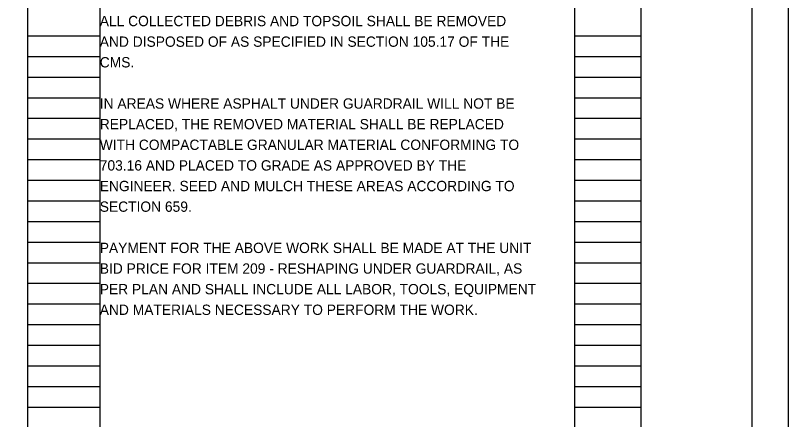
# Model space of a CAD drawing. Extents: x 0 to 34, y 0 to 22.
# Drawn here: x 23.51 to 34, y 5.57 to 11.06 of the extents above; entities that cross this region are included whole.
import ezdxf

# ---------------------------------------------------------------- set-up
doc = ezdxf.new("R2010")
doc.units = 0
for name, color, linetype in [('SH_Border', 7, 'Continuous'), ('SH_Cut_Line', 7, 'Continuous'), ('SH_Data', 7, 'Continuous'), ('SH_Text', 7, 'Continuous')]:
    doc.layers.add(name, color=color, linetype=linetype)

msp = doc.modelspace()

# ---------------------------------------------------------------- linework, layer by layer
at = {"layer": 'SH_Border'}
msp.add_line((32, 0.5), (32, 21.5), dxfattribs=at)
msp.add_lwpolyline([(1.5, 21.5), (33.5, 21.5), (33.5, 0.5), (1.5, 0.5)], close=True, dxfattribs=at)
at = {"layer": 'SH_Cut_Line'}
msp.add_lwpolyline([(0, 0), (34, 0), (34, 22), (0, 22)], close=True, dxfattribs=at)
at = {"layer": 'SH_Data'}
for p, q in [((23.68, 0.98), (23.68, 21.14)), ((24.66, 0.98), (24.66, 21.14)), ((31.1, 0.98), (31.1, 21.14)), ((32, 0.98), (32, 21.14)), ((23.68, 10.78), (24.66, 10.78)), ((31.1, 10.78), (32, 10.78)), ((23.68, 10.5), (24.66, 10.5)), ((31.1, 10.5), (32, 10.5)), ((23.68, 10.22), (24.66, 10.22)), ((31.1, 10.22), (32, 10.22)), ((23.68, 9.94), (24.66, 9.94)), ((31.1, 9.94), (32, 9.94)), ((23.68, 9.66), (24.66, 9.66)), ((31.1, 9.66), (32, 9.66)), ((23.68, 9.38), (24.66, 9.38)), ((31.1, 9.38), (32, 9.38)), ((23.68, 9.1), (24.66, 9.1)), ((31.1, 9.1), (32, 9.1)), ((23.68, 8.82), (24.66, 8.82)), ((31.1, 8.82), (32, 8.82)), ((23.68, 8.54), (24.66, 8.54)), ((31.1, 8.54), (32, 8.54)), ((23.68, 8.26), (24.66, 8.26)), ((31.1, 8.26), (32, 8.26)), ((23.68, 7.98), (24.66, 7.98)), ((31.1, 7.98), (32, 7.98)), ((23.68, 7.7), (24.66, 7.7)), ((31.1, 7.7), (32, 7.7)), ((23.68, 7.42), (24.66, 7.42)), ((31.1, 7.42), (32, 7.42)), ((23.68, 7.14), (24.66, 7.14)), ((31.1, 7.14), (32, 7.14)), ((23.68, 6.86), (24.66, 6.86)), ((31.1, 6.86), (32, 6.86)), ((23.68, 6.58), (24.66, 6.58)), ((31.1, 6.58), (32, 6.58)), ((23.68, 6.3), (24.66, 6.3)), ((31.1, 6.3), (32, 6.3)), ((23.68, 6.02), (24.66, 6.02)), ((31.1, 6.02), (32, 6.02)), ((23.68, 5.74), (24.66, 5.74)), ((31.1, 5.74), (32, 5.74))]:
    msp.add_line(p, q, dxfattribs=at)

# ---------------------------------------------------------------- texts
at = {"layer": 'SH_Text'}
for s, p in [('ALL COLLECTED DEBRIS AND TOPSOIL SHALL BE REMOVED ', (24.656, 10.911)), ('AND DISPOSED OF AS SPECIFIED IN SECTION 105.17 OF THE ', (24.656, 10.631)), ('CMS.', (24.656, 10.351)), ('IN AREAS WHERE ASPHALT UNDER GUARDRAIL WILL NOT BE ', (24.656, 9.791)), ('REPLACED, THE REMOVED MATERIAL SHALL BE REPLACED ', (24.656, 9.511)), ('WITH COMPACTABLE GRANULAR MATERIAL CONFORMING TO ', (24.656, 9.231)), ('703.16 AND PLACED TO GRADE AS APPROVED BY THE ', (24.656, 8.951)), ('ENGINEER. SEED AND MULCH THESE AREAS ACCORDING TO ', (24.656, 8.671)), ('SECTION 659. ', (24.656, 8.391)), ('PAYMENT FOR THE ABOVE WORK SHALL BE MADE AT THE UNIT ', (24.656, 7.831)), ('BID PRICE FOR ITEM 209 - RESHAPING UNDER GUARDRAIL, AS ', (24.656, 7.551)), ('PER PLAN AND SHALL INCLUDE ALL LABOR, TOOLS, EQUIPMENT ', (24.656, 7.271)), ('AND MATERIALS NECESSARY TO PERFORM THE WORK.', (24.656, 6.991))]:
    msp.add_text(s, height=0.14, dxfattribs=at).set_placement(p)

doc.saveas('drawing.dxf')
